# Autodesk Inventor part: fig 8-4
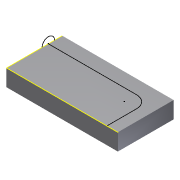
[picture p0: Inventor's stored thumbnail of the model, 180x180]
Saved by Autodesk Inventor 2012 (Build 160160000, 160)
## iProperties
Created: 2009-04
Part Number: fig 8-4
Document SubType Name: Modeling
Designer: Sham
Density: 1 g/cm^3
Material: Default
Author: Sham
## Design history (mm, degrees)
sketch "Sketch1"
  geometry: L1 (-20, 20)-(20, 20); L2 (20, 20)-(20, 0); L3 (20, 0)-(-20, 0); L4 (-20, 0)-(-20, 20)
  constraints: 8 end point
extrude "Extrusion1" new body sketch "Sketch1" distance "d0" = 6; taper "d1" = 0 deg
sketch "Sketch4"
  geometry: L1 (6, 0)-(6, 20) reference; C1 r 2.236 at (6, 15)
  constraints: 1 centre point, 1 point on line
sketch "Sketch5"
  geometry: L1 (-20, 0)-(-20, 20) reference; L2 (20, 0)-(-20, 0) reference; L3 (-20, 15)-(11.667, 15); L4 (16, 10.667)-(16, 0); A1 r 4.333 centre (11.667, 10.667) between (16, 10.667) and (11.667, 15)
  constraints: 4 end point, 2 point on circle, 2 point on line, 1 centre point, 1 tangent
body "Solid1"
